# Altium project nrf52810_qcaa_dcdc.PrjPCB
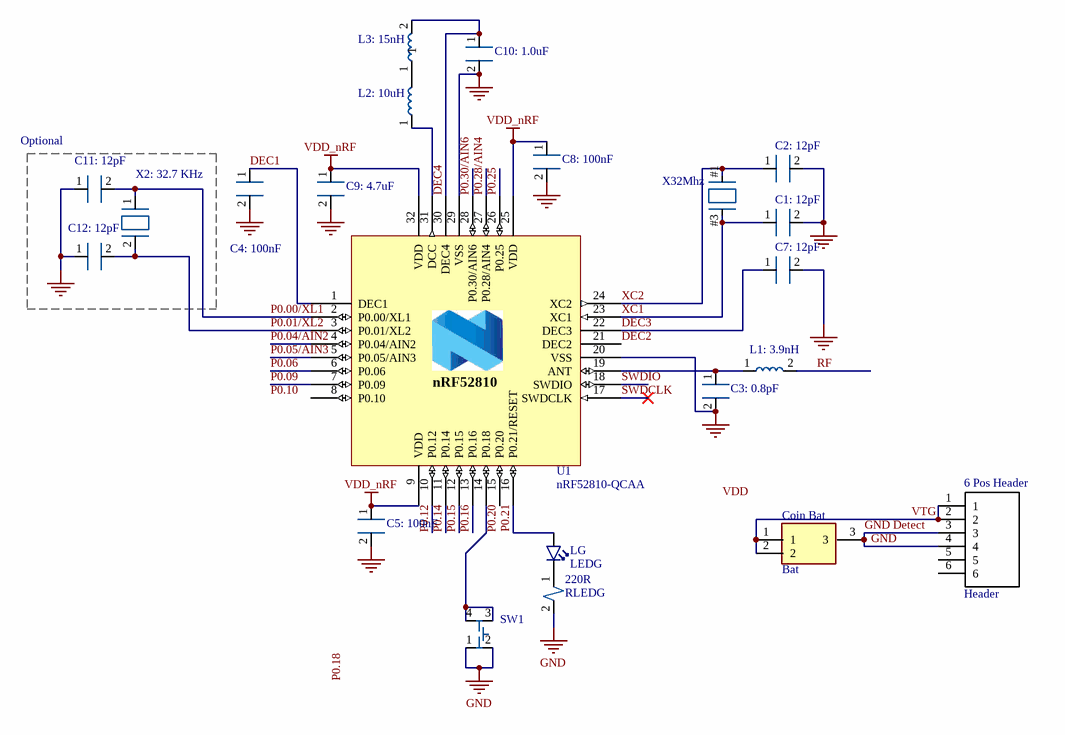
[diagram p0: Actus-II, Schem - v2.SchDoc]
1 sheet, 22 parts. Net scope: global (net labels, ports and power ports of the same name join across sheets).
Board file: Actus-II, PCB - v2.PcbDoc

## Sheet Actus-II, Schem - v2.SchDoc: nRF52810-QCAA Reference Layout (DCDC)
size A4; Revision: 1.0; SheetNumber: 1; SheetTotal: 1; DrawnBy: RUBR; DocumentSize: A4; PCAName: nRF52810-QCAA Reference Layout (DCDC)

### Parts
6_Pos_Header  Header  [Header]
220R  RLEDG  [RLEDG]
C1:_12pF  CC0402GRNPO9BN120  [CC0402GRNPO9BN120]  (value not drawn)
C2:_12pF  CC0402GRNPO9BN120  [CC0402GRNPO9BN120]  (value not drawn)
C3:_0.8pF  201R07S0R8AV4T  [201R07S0R8AV4T]  (value not drawn)
C4:_100nF  CC0402KRX7R7BB104  [CC0402KRX7R7BB104]  (value not drawn)
C5:_100nF  CC0402KRX7R7BB104  [CC0402KRX7R7BB104]  (value not drawn)
C7:_12pF  C0402C101J5GAC7411  [C0402C101J5GAC7411]  (value not drawn)
C8:_100nF  CC0402KRX7R7BB104  [CC0402KRX7R7BB104]  (value not drawn)
C9:_4.7uF  JMK107BJ475KA-T  [JMK107BJ475KA-T]  (value not drawn)
C10:_1.0uF  CC0603KRX7R7BB105  [CC0603KRX7R7BB105]  (value not drawn)
C11:_12pF  CC0402GRNPO9BN120  [CC0402GRNPO9BN120]  (value not drawn)
C12:_12pF  CC0402GRNPO9BN120  [CC0402GRNPO9BN120]  (value not drawn)
Coin_Bat  Bat  [Bat]
L1:_3.9nH  LQP15MN3N9B02D  [LQP15MN3N9B02D]  (value not drawn)
L2:_10uH  MLZ1608N100LT000  [MLZ1608N100LT000]  (value not drawn)
L3:_15nH  HK100515NJ-T  [HK100515NJ-T]  (value not drawn)
LG  LEDG  [LEDG]
SW1  KMT021 NGJ LHS  [Switch]  (value not drawn)
U1  nRF52810-QCAA  [Nordic_QFN50P500X500X90-33N]
X2:_32.7_KHz  FC-135R 32.7680KA-AC3  [FC-135R 32.7680KA-AC3]  (value not drawn)
X32Mhz  Q22FA12800025  [Q22FA12800025]  (value not drawn)

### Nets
GND: 6_Pos_Header.3 6_Pos_Header.4 220R.2 C1:_12pF.2 C2:_12pF.2 C3:_0.8pF.2 C4:_100nF.2 C5:_100nF.2 C7:_12pF.2 C8:_100nF.2 C9:_4.7uF.2 C10:_1.0uF.2 C11:_12pF.1 C12:_12pF.1 Coin_Bat.3 SW1.1 SW1.2 U1.20(VSS) U1.29(VSS) U1.33  [also labelled GND Detect]
VDD_nRF: C5:_100nF.1 C8:_100nF.1 C9:_4.7uF.1 U1.9(VDD) U1.25(VDD) U1.32(VDD)
DEC1: C4:_100nF.1 U1.1(DEC1)
DEC2: U1.21(DEC2)
DEC3: C7:_12pF.1 U1.22(DEC3)
DEC4: C10:_1.0uF.1 L3:_15nH.2 U1.30(DEC4)
P0.00/XL1: C11:_12pF.2 U1.2(P0.00/XL1) X2:_32.7_KHz.1
P0.01/XL2: C12:_12pF.2 U1.3(P0.01/XL2) X2:_32.7_KHz.2
P0.04/AIN2: U1.4(P0.04/AIN2)
P0.05/AIN3: U1.5(P0.05/AIN3)
P0.06: U1.6(P0.06)
P0.09: U1.7(P0.09)
P0.12: U1.10(P0.12)
P0.14: U1.11(P0.14)
P0.15: U1.12(P0.15)
P0.16: U1.13(P0.16)
P0.21: LG.2(A) U1.16(P0.21/RESET)
P0.25: U1.26(P0.25)
P0.28/AIN4: U1.27(P0.28/AIN4)
P0.30/AIN6: U1.28(P0.30/AIN6)
RF: L1:_3.9nH.2
SWDCLK: U1.17(SWDCLK)
SWDIO: U1.18(SWDIO)
VTG: 6_Pos_Header.1 6_Pos_Header.2 Coin_Bat.1 Coin_Bat.2
XC1: C1:_12pF.1 U1.23(XC1) X32Mhz.#3
XC2: C2:_12pF.1 U1.24(XC2) X32Mhz.#1
Net220R_1: 220R.1 LG.1(C)
NetC3:_0.8pF_1: C3:_0.8pF.1 L1:_3.9nH.1 U1.19(ANT)
NetL2:_10uH_1: L2:_10uH.1 U1.31(DCC)
NetL2:_10uH_2: L2:_10uH.2 L3:_15nH.1
NetSW1_3: SW1.3 SW1.4 U1.14(P0.18)

Not connected (* = marked no-connect by the designer): 6_Pos_Header 5 6; U1 8(P0.10) 15(P0.20)

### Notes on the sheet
- (near C11:_12pF) Optional
- Labels drawn without touching a wire or pin: P0.10, P0.18, P0.20, VDD

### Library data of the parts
C1:_12pF C2:_12pF C11:_12pF C12:_12pF = CC0402GRNPO9BN120: C1, C2, C11, C12:  12pF, 0402, Yageo
C3:_0.8pF = 201R07S0R8AV4T: C3: 0.8pF, 0402, Johanson Dielectrics
C4:_100nF C5:_100nF C8:_100nF = CC0402KRX7R7BB104: C4, C5, C8 : 100nF (0.1uF), 0402, Yageo
C7:_12pF = C0402C101J5GAC7411: C7: 100 pF, 0402, KEMET
C9:_4.7uF = JMK107BJ475KA-T: C9: 4.7uF, 0603, Taiyo Yuden
C10:_1.0uF = CC0603KRX7R7BB105: C10: 1.0uF, 0603, Yageo
L1:_3.9nH = LQP15MN3N9B02D: L1: 3.9 nH, 0402 (1005 metric), Murata Electronics
L2:_10uH = MLZ1608N100LT000: L2: 10 uH, 0603 (1608 metric), TDK
L3:_15nH = HK100515NJ-T: L3: 15nH, 0402, Taiyo Yuden
SW1 = KMT021 NGJ LHS: Micro-Switch
U1 = nRF52810-QCAA: Multi-protocol Bluetooth Low Energy, ANT and 2.4GHz proprietary system-on-chip; Manufacturer: Nordic Semiconductor; Note: nRF52810 - QFN32 5x5 0.5mm pitch
X2:_32.7_KHz = FC-135R 32.7680KA-AC3: X2: 32.7680KHZ, XTAL_3215, EPSON
X32Mhz = Q22FA12800025: X1: 32MHz, XTAL_2016, EPSON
